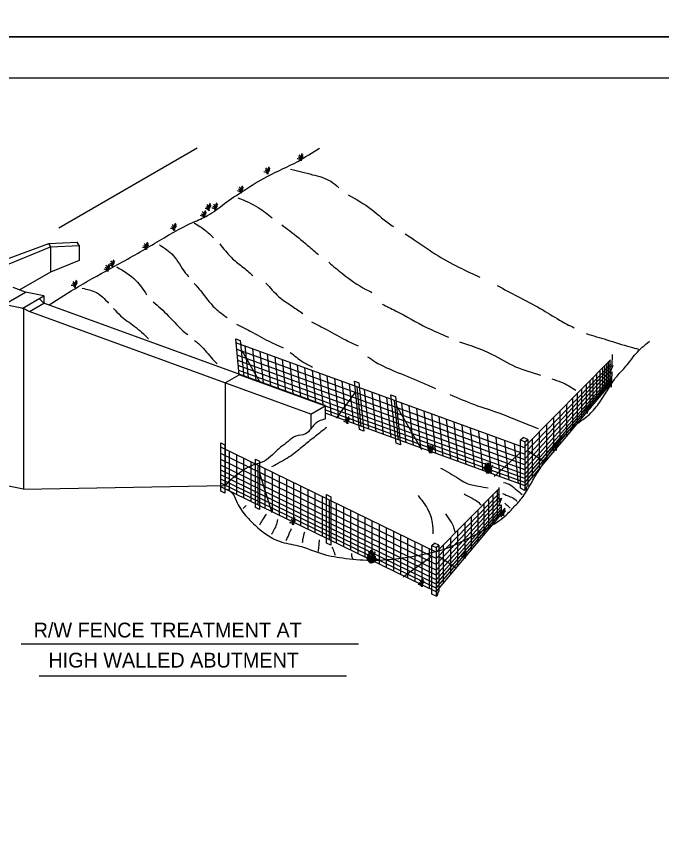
# Model space of a CAD drawing. Extents: x 13 to 918, y -903 to 879.
# Drawn here: x 134.4 to 370, y -602.3 to -301.6 of the extents above; entities that cross this region are included whole.
import ezdxf

# ---------------------------------------------------------------- set-up
doc = ezdxf.new("R2010")
doc.units = 0
for name, color, linetype in [('1', 7, 'Continuous'), ('3', 7, 'Continuous'), ('PLT-BNDY', 7, 'Continuous')]:
    doc.layers.add(name, color=color, linetype=linetype)

msp = doc.modelspace()

# ---------------------------------------------------------------- linework, layer by layer
at = {"layer": '1'}
for p, q in [((146.07275, -384.56525), (156.61225, -384.013)), ((146.904, -385.75275), (146.1915, -384.5215)), ((157.302, -385.20675), (156.61225, -384.013)), ((146.88525, -385.7215), (146.88525, -394.9485)), ((146.904, -385.75275), (157.302, -385.20675)), ((157.302, -385.20675), (157.302, -390.711)), ((136.52275, -408.234), (144.36025, -403.70675)), ((144.36025, -406.361), (142.68725, -404.62975)), ((144.36025, -403.70675), (144.36025, -406.361)), ((136.93525, -408.3235), (136.93525, -474.34425)), ((139.06225, -409.4215), (136.93525, -408.3235)), ((139.19775, -409.34225), (144.36025, -406.361)), ((215.77475, -432.48175), (214.53325, -419.409)), ((214.53325, -419.409), (216.07275, -419.9735)), ((216.07275, -419.9735), (217.479, -433.159)), ((216.6895, -423.60475), (223.18525, -434.8965)), ((217.86225, -421.92775), (219.079, -433.49425)), ((220.57475, -423.00475), (221.78325, -434.49225)), ((223.29775, -423.9965), (224.50825, -435.48175)), ((226.02275, -424.99025), (227.23725, -436.534)), ((228.7435, -425.97975), (229.95825, -437.511)), ((231.4665, -426.96725), (232.68725, -438.588)), ((352.004, -425.09425), (351.8915, -429.234)), ((234.1935, -427.963), (235.402, -439.461)), ((236.9145, -428.95275), (238.13325, -440.536)), ((239.6415, -429.94425), (240.8435, -441.39025)), ((348.454, -430.0255), (348.454, -439.4255)), ((349.14775, -429.3235), (349.14775, -438.50275)), ((349.85825, -428.60475), (349.85825, -437.69425)), ((350.51225, -427.94225), (350.51225, -436.79025)), ((351.18725, -427.259), (351.18725, -436.136)), ((210.61225, -435.463), (215.77475, -432.48175)), ((242.36225, -430.934), (243.57475, -442.4755)), ((245.08725, -431.92775), (246.28725, -443.361)), ((247.81025, -432.91925), (249.32475, -447.31925)), ((346.26225, -432.24225), (346.26225, -442.00275)), ((347.43525, -431.05675), (347.43525, -440.6965)), ((351.829, -431.5235), (351.679, -437.06925)), ((210.61225, -435.463), (210.61225, -472.91925)), ((250.53525, -433.90675), (252.04775, -448.311)), ((253.25825, -434.9005), (254.77075, -449.30275)), ((255.981, -435.89225), (257.4935, -450.29425)), ((259.68325, -452.4755), (257.829, -434.861)), ((257.829, -434.861), (259.4665, -435.45675)), ((259.4665, -435.45675), (261.3165, -453.06925)), ((343.781, -434.75475), (343.781, -444.888)), ((344.89575, -433.6255), (344.89575, -443.58175)), ((258.28525, -438.763), (251.18325, -448.2965)), ((258.702, -436.884), (260.2165, -451.286)), ((261.429, -437.8755), (262.9415, -452.2755)), ((264.14975, -438.86525), (265.6645, -453.26925)), ((340.8435, -437.7255), (340.8435, -448.38175)), ((342.44775, -436.10275), (342.44775, -446.53175)), ((266.877, -439.859), (268.3895, -454.259)), ((269.59775, -440.8465), (271.11225, -455.2505)), ((273.03325, -457.47775), (271.179, -439.863)), ((271.179, -439.863), (272.8165, -440.459)), ((272.32275, -441.84025), (273.83525, -456.24225)), ((272.8165, -440.459), (274.6665, -458.0715)), ((337.49775, -441.113), (337.49775, -452.534)), ((339.256, -439.33175), (339.256, -450.25675)), ((241.93525, -446.861), (247.09775, -443.87975)), ((247.1395, -443.76725), (247.1395, -448.6985)), ((273.302, -444.0715), (282.3645, -459.81925)), ((275.04575, -442.82975), (276.56025, -457.23175)), ((277.77075, -443.8215), (279.28325, -458.2255)), ((280.4935, -444.81525), (282.006, -459.21525)), ((335.29575, -443.34025), (335.29575, -455.14025)), ((241.93525, -446.861), (241.93525, -452.2215)), ((283.2165, -445.80475), (284.731, -460.209)), ((285.93725, -446.79425), (287.452, -461.1985)), ((288.6645, -447.79025), (290.179, -462.19025)), ((332.8665, -445.7985), (332.8665, -458.011)), ((291.38525, -448.77775), (292.89975, -463.17975)), ((294.11225, -449.76925), (295.62075, -464.138)), ((297.056, -450.9235), (298.5645, -465.29225)), ((327.9435, -450.77975), (327.9435, -463.85675)), ((330.54975, -448.14225), (330.54975, -460.7505)), ((261.3165, -453.06925), (259.68325, -452.4755)), ((300.17075, -452.0215), (301.679, -466.39025)), ((303.21025, -453.1755), (304.7185, -467.54425)), ((325.3395, -453.41525), (325.3395, -466.961)), ((306.327, -454.32975), (307.83525, -468.6985)), ((309.4435, -455.484), (310.952, -469.85275)), ((312.7145, -456.57975), (314.22275, -470.9485)), ((318.554, -473.961), (318.554, -456.25275)), ((318.554, -456.25275), (320.1165, -457.01525)), ((320.1165, -457.01525), (320.1165, -474.7235)), ((321.1415, -456.159), (321.1415, -472.938)), ((322.73325, -456.05275), (322.73325, -470.06525)), ((208.99775, -475.0255), (208.99775, -457.31725)), ((208.99775, -457.31725), (210.56025, -458.07975)), ((210.56025, -458.07975), (210.56025, -475.788)), ((274.6665, -458.0715), (273.03325, -457.47775)), ((316.19575, -457.811), (317.704, -472.17975)), ((320.129, -458.688), (320.129, -471.86525)), ((321.10825, -460.14425), (327.40825, -464.32975)), ((212.14975, -460.49225), (212.14975, -474.9735)), ((214.756, -461.763), (214.756, -476.24425)), ((217.36025, -463.034), (217.36025, -477.51525)), ((318.552, -460.886), (308.8665, -469.61525)), ((219.9665, -464.30475), (219.9665, -478.786)), ((221.652, -481.013), (221.652, -463.30475)), ((221.652, -463.30475), (223.2145, -464.06725)), ((222.57075, -465.5755), (222.57075, -480.05675)), ((223.2145, -464.06725), (223.2145, -481.7755)), ((223.227, -468.42975), (227.729, -482.85675)), ((225.17475, -466.84425), (225.17475, -481.3255)), ((227.781, -468.11525), (227.781, -482.5965)), ((230.38525, -469.386), (230.38525, -483.86725)), ((232.9915, -470.65675), (232.9915, -485.138)), ((235.59575, -471.92775), (235.59575, -486.409)), ((136.93525, -474.34425), (210.61225, -472.91925)), ((210.56025, -475.788), (208.99775, -475.0255)), ((238.19975, -473.1985), (238.19975, -487.67975)), ((240.806, -474.46925), (240.806, -488.9505)), ((310.0145, -474.8255), (310.0145, -485.18175)), ((310.61225, -473.63175), (310.61225, -478.05275)), ((320.1165, -474.7235), (318.554, -473.961)), ((243.41025, -475.738), (243.41025, -490.21925)), ((246.0165, -477.009), (246.0165, -491.49025)), ((247.6935, -493.984), (247.6935, -476.2755)), ((247.6935, -476.2755), (249.256, -477.038)), ((249.256, -477.038), (249.256, -494.7465)), ((306.82275, -477.98175), (306.82275, -488.90675)), ((308.41025, -476.3755), (308.41025, -487.03175)), ((223.2145, -481.7755), (221.652, -481.013)), ((248.62075, -478.27975), (248.62075, -492.761)), ((251.22475, -479.5505), (251.22475, -494.03175)), ((253.831, -480.8215), (253.831, -495.30275)), ((305.0645, -479.763), (305.0645, -491.184)), ((311.42275, -479.9715), (311.42275, -484.51925)), ((256.43525, -482.09225), (256.43525, -496.5735)), ((259.0415, -483.363), (259.0415, -497.84425)), ((302.86225, -481.99025), (302.86225, -493.79025)), ((261.64575, -484.63175), (261.64575, -499.113)), ((264.24975, -485.90275), (264.24975, -500.384)), ((266.856, -487.1735), (266.856, -501.65475)), ((298.1165, -486.79225), (298.1165, -499.4005)), ((300.43325, -484.4485), (300.43325, -496.661)), ((269.46025, -488.44425), (269.46025, -502.9255)), ((272.0665, -489.71525), (272.0665, -504.1965)), ((295.51025, -489.42975), (295.51025, -502.50675)), ((274.67075, -490.986), (274.67075, -505.46725)), ((277.27475, -492.25475), (277.27475, -506.736)), ((292.906, -492.06525), (292.906, -505.611)), ((249.256, -494.7465), (247.6935, -493.984)), ((279.881, -493.52775), (279.881, -508.009)), ((282.48525, -494.7965), (282.48525, -509.27775)), ((285.0915, -496.06725), (285.0915, -510.51525)), ((286.12075, -512.611), (286.12075, -494.90275)), ((286.12075, -494.90275), (287.68325, -495.66525)), ((287.68325, -495.66525), (287.68325, -513.3735)), ((288.70825, -494.809), (288.70825, -511.588)), ((290.29975, -494.70275), (290.29975, -508.71525)), ((286.1915, -498.75275), (275.64775, -506.4215)), ((287.69575, -497.338), (287.69575, -510.51525)), ((288.67475, -498.79425), (294.97475, -502.97975)), ((287.68325, -513.3735), (286.12075, -512.611))]:
    msp.add_line(p, q, dxfattribs=at)
for points in [[(837.2505, -888.06975), (837.2505, -324.06975), (51.2505, -324.06975), (51.2505, -888.06975), (837.2505, -888.06975), (837.2505, -861.71075), (637.2505, -861.71075), (637.2505, -797.03325), (837.2505, -797.03325), (837.2505, -768.06975), (637.2505, -768.06975), (637.2505, -888.06975), (716.052, -888.06975), (716.052, -861.71075), (716.052, -888.06975), (793.052, -888.06975), (793.052, -861.71075), (793.052, -874.02725), (837.2505, -874.02725)], [(351.2935, -429.47975), (352.24975, -429.05275), (351.1915, -431.80675), (352.14775, -431.37975)], [(306.62275, -468.59225), (308.2185, -465.5715), (306.277, -468.41925), (307.58325, -464.99425), (306.58325, -468.55275), (306.9685, -464.686), (306.3145, -468.34225), (306.277, -464.66725), (306.6415, -468.51525), (305.62275, -464.763), (306.277, -468.45675), (305.429, -465.8215), (306.681, -468.45675), (305.27475, -466.611), (306.23725, -468.45675), (308.04575, -466.59225), (306.54575, -468.4965), (308.19975, -467.59225), (306.23725, -468.361)], [(320.1165, -474.686), (320.5685, -474.45475), (320.68525, -474.0715), (320.72275, -473.59025), (320.954, -473.3215), (321.0685, -473.03175), (321.1415, -472.91725)], [(310.5685, -478.0715), (311.52475, -477.64425), (310.4665, -480.3985), (311.42275, -479.9715)], [(287.68325, -513.336), (288.13525, -513.10475), (288.252, -512.7215), (288.2895, -512.24025), (288.52075, -511.9715), (288.63525, -511.68175), (288.70825, -511.56725)]]:
    msp.add_lwpolyline(points, dxfattribs=at)
for centre, radius, start, end in [((240.74523, -353.29065), 2.54574, 139.3976806, 202.1514389), ((236.91991, -355.22506), 1.68722, 34.5049889, 89.1232639), ((237.13052, -354.07945), 1.15481, 346.635825, 79.9956111), ((236.0146, -353.71526), 2.32168, 344.7066778, 44.9317139), ((239.81735, -354.14027), 1.53965, 118.5656389, 187.6931111), ((241.70484, -354.22605), 3.37523, 142.0984694, 181.7245194), ((224.99302, -358.92737), 1.15481, 346.635825, 79.9956111), ((223.8771, -358.56317), 2.32168, 344.7066778, 44.9317139), ((228.60773, -358.13857), 2.54574, 139.3976806, 202.1514389), ((227.67985, -358.98818), 1.53965, 118.5656389, 187.6931111), ((229.56734, -359.07397), 3.37523, 142.0984694, 181.7245194), ((224.78241, -360.07298), 1.68722, 34.5049889, 89.1232639), ((214.16251, -365.50692), 2.32168, 344.7066778, 44.9317139), ((218.89315, -365.08232), 2.54574, 139.3976806, 202.1514389), ((215.06782, -367.01673), 1.68722, 34.5049889, 89.1232639), ((215.27844, -365.87112), 1.15481, 346.635825, 79.9956111), ((217.96526, -365.93193), 1.53965, 118.5656389, 187.6931111), ((219.85276, -366.01772), 3.37523, 142.0984694, 181.7245194), ((207.10148, -371.48857), 2.54574, 139.3976806, 202.1514389), ((209.54315, -371.31565), 2.54574, 139.3976806, 202.1514389), ((200.6396, -374.52984), 2.32168, 344.7066778, 44.9317139), ((205.37023, -374.10524), 2.54574, 139.3976806, 202.1514389), ((203.27616, -373.42298), 1.68722, 34.5049889, 89.1232639), ((203.48677, -372.27737), 1.15481, 346.635825, 79.9956111), ((202.37085, -371.91317), 2.32168, 344.7066778, 44.9317139), ((206.1736, -372.33818), 1.53965, 118.5656389, 187.6931111), ((208.06109, -372.42397), 3.37523, 142.0984694, 181.7245194), ((205.71782, -373.25006), 1.68722, 34.5049889, 89.1232639), ((205.92844, -372.10445), 1.15481, 346.635825, 79.9956111), ((204.81251, -371.74026), 2.32168, 344.7066778, 44.9317139), ((208.61526, -372.16527), 1.53965, 118.5656389, 187.6931111), ((210.50276, -372.25105), 3.37523, 142.0984694, 181.7245194), ((201.54491, -376.03965), 1.68722, 34.5049889, 89.1232639), ((201.75552, -374.89404), 1.15481, 346.635825, 79.9956111), ((204.44235, -374.95485), 1.53965, 118.5656389, 187.6931111), ((206.32984, -375.04063), 3.37523, 142.0984694, 181.7245194), ((190.84719, -379.56695), 1.15481, 346.635825, 79.9956111), ((189.73126, -379.20276), 2.32168, 344.7066778, 44.9317139), ((194.4619, -378.77815), 2.54574, 139.3976806, 202.1514389), ((193.53401, -379.62777), 1.53965, 118.5656389, 187.6931111), ((195.42151, -379.71355), 3.37523, 142.0984694, 181.7245194), ((190.63657, -380.71256), 1.68722, 34.5049889, 89.1232639), ((179.49793, -386.12984), 2.32168, 344.7066778, 44.9317139), ((184.22857, -385.70524), 2.54574, 139.3976806, 202.1514389), ((185.18818, -386.64063), 3.37523, 142.0984694, 181.7245194), ((180.40324, -387.63965), 1.68722, 34.5049889, 89.1232639), ((180.61386, -386.49404), 1.15481, 346.635825, 79.9956111), ((183.30068, -386.55485), 1.53965, 118.5656389, 187.6931111), ((167.18543, -392.55484), 2.32168, 344.7066778, 44.9317139), ((171.91607, -392.13024), 2.54574, 139.3976806, 202.1514389), ((166.35949, -395.6209), 1.68722, 34.5049889, 89.1232639), ((166.57011, -394.47529), 1.15481, 346.635825, 79.9956111), ((165.45418, -394.11109), 2.32168, 344.7066778, 44.9317139), ((170.18482, -393.68649), 2.54574, 139.3976806, 202.1514389), ((169.25693, -394.5361), 1.53965, 118.5656389, 187.6931111), ((171.14443, -394.62188), 3.37523, 142.0984694, 181.7245194), ((168.09074, -394.06465), 1.68722, 34.5049889, 89.1232639), ((168.30136, -392.91904), 1.15481, 346.635825, 79.9956111), ((170.98818, -392.97985), 1.53965, 118.5656389, 187.6931111), ((172.87568, -393.06563), 3.37523, 142.0984694, 181.7245194), ((154.39491, -401.5084), 1.68722, 34.5049889, 89.1232639), ((154.60552, -400.36279), 1.15481, 346.635825, 79.9956111), ((153.4896, -399.99859), 2.32168, 344.7066778, 44.9317139), ((158.22023, -399.57399), 2.54574, 139.3976806, 202.1514389), ((157.29235, -400.4236), 1.53965, 118.5656389, 187.6931111), ((159.17984, -400.50938), 3.37523, 142.0984694, 181.7245194), ((340.79262, -446.03759), 1.97401, 340.3763778, 56.4624917), ((337.53479, -445.41441), 5.30578, 346.3887194, 18.8456472), ((345.42541, -445.59079), 2.73341, 125.7872472, 200.4625444), ((345.24911, -446.22664), 2.46318, 129.7876167, 190.205025), ((257.73273, -449.33857), 2.54574, 139.3976806, 202.1514389), ((341.12625, -447.03952), 1.70327, 12.7696972, 59.9544917), ((253.90741, -451.27298), 1.68722, 34.5049889, 89.1232639), ((254.11802, -450.12737), 1.15481, 346.635825, 79.9956111), ((253.0021, -449.76317), 2.32168, 344.7066778, 44.9317139), ((256.80485, -450.18818), 1.53965, 118.5656389, 187.6931111), ((258.69234, -450.27397), 3.37523, 142.0984694, 181.7245194), ((336.05809, -459.22027), 4.6144, 144.0455, 192.5566278), ((280.94652, -462.14109), 4.99917, 11.477125, 44.0518528), ((262.0893, -467.8557), 24.25855, 16.1942278, 22.2630333), ((251.95983, -464.84735), 33.62974, 6.3182278, 11.4283389), ((275.78806, -461.73646), 9.86983, 3.87595, 20.7342222), ((292.74066, -460.66782), 7.44782, 161.6192222, 183.6840556), ((287.12805, -460.85639), 1.55615, 91.1135861, 190.0377389), ((295.87435, -459.95762), 10.29921, 170.6355361, 186.1964472), ((288.75293, -460.46429), 2.98614, 135.1656, 193.2039417), ((287.89253, -461.23684), 2.07234, 110.8760639, 175.3625472), ((290.95729, -460.57271), 4.85599, 152.8772472, 186.7845), ((329.56301, -460.00959), 1.92587, 353.6243139, 68.0395306), ((329.0399, -459.24325), 2.61305, 338.852575, 40.9169944), ((339.06378, -461.40083), 7.7538, 150.3862972, 171.2661556), ((333.70568, -460.09978), 2.1929, 126.5456194, 182.2521944), ((310.82824, -484.86048), 1.68722, 34.5049889, 89.1232639), ((311.03886, -483.71487), 1.15481, 346.635825, 79.9956111), ((309.92293, -483.35067), 2.32168, 344.7066778, 44.9317139), ((314.65357, -482.92607), 2.54574, 139.3976806, 202.1514389), ((313.72568, -483.77568), 1.53965, 118.5656389, 187.6931111), ((315.61318, -483.86147), 3.37523, 142.0984694, 181.7245194), ((234.13241, -488.26465), 1.68722, 34.5049889, 89.1232639), ((234.34302, -487.11904), 1.15481, 346.635825, 79.9956111), ((233.2271, -486.75484), 2.32168, 344.7066778, 44.9317139), ((237.95773, -486.33024), 2.54574, 139.3976806, 202.1514389), ((237.02985, -487.17985), 1.53965, 118.5656389, 187.6931111), ((238.91734, -487.26563), 3.37523, 142.0984694, 181.7245194), ((296.80532, -500.51881), 1.68722, 34.5049889, 89.1232639), ((297.01594, -499.3732), 1.15481, 346.635825, 79.9956111), ((295.90001, -499.00901), 2.32168, 344.7066778, 44.9317139), ((300.63065, -498.5844), 2.54574, 139.3976806, 202.1514389), ((299.70276, -499.43402), 1.53965, 118.5656389, 187.6931111), ((301.59026, -499.5198), 3.37523, 142.0984694, 181.7245194), ((280.1646, -509.30067), 2.32168, 344.7066778, 44.9317139), ((284.89523, -508.87607), 2.54574, 139.3976806, 202.1514389), ((285.85484, -509.81147), 3.37523, 142.0984694, 181.7245194), ((281.06991, -510.81048), 1.68722, 34.5049889, 89.1232639), ((281.28052, -509.66487), 1.15481, 346.635825, 79.9956111), ((283.96735, -509.72568), 1.53965, 118.5656389, 187.6931111)]:
    msp.add_arc(centre, radius, start, end, dxfattribs=at)
for points in [[(146.30825, -406.98175), (157.056, -400.2255), (170.40825, -392.74225), (184.9685, -384.4505), (198.9165, -376.7755), (204.1685, -374.3505), (210.4395, -369.90675), (217.32475, -365.25275), (226.02075, -360.0005), (237.1395, -354.538), (245.027, -349.6715)], [(234.5415, -357.384), (242.5645, -359.386), (249.181, -361.79025), (252.204, -364.12975)], [(255.53525, -366.686), (264.01225, -372.0235), (271.631, -378.0255), (272.12475, -378.336)], [(215.306, -367.811), (222.731, -371.409), (227.77475, -375.1255)], [(199.281, -377.0255), (203.28325, -379.64225), (206.3665, -382.4735)], [(231.32075, -377.7485), (234.1395, -379.834), (240.756, -385.24025), (244.73725, -388.64425)], [(276.352, -380.99425), (278.63325, -382.42975), (287.252, -388.259), (296.081, -393.261), (303.6915, -396.79025)], [(208.679, -384.6985), (212.902, -389.64425), (216.7685, -392.8755), (220.78725, -396.28175)], [(186.6435, -385.0465), (191.6645, -388.85475), (196.0685, -395.261), (197.34575, -396.76525)], [(171.02275, -393.06925), (178.02475, -398.06925), (181.9395, -403.22975)], [(248.44775, -391.3985), (253.606, -395.66525), (262.01225, -401.28175), (264.252, -402.4005)], [(199.329, -399.10275), (201.68525, -401.87975), (206.879, -408.09225), (211.3415, -411.60675)], [(225.43525, -398.963), (225.5395, -399.06925), (230.156, -403.87975), (235.15825, -407.4755), (238.97475, -410.05675)], [(310.002, -399.911), (317.529, -403.87975), (325.7435, -408.284), (332.7645, -412.4985), (338.1145, -415.36525)], [(158.38525, -400.87775), (163.59775, -402.4755), (168.002, -406.284)], [(184.32475, -405.85475), (189.856, -410.9005), (194.6645, -415.90275), (196.96025, -417.82775)], [(169.88725, -408.259), (172.40825, -410.9005), (177.429, -414.709), (182.6415, -419.30675)], [(267.952, -406.661), (272.82275, -409.09225), (284.46225, -415.30675), (292.256, -418.76525)], [(214.802, -413.9735), (220.5185, -416.90275), (227.5395, -420.711), (231.8165, -422.709)], [(242.15825, -413.16525), (247.87475, -416.09425), (254.89575, -419.90275), (259.17275, -421.9005)], [(342.5435, -417.46525), (350.002, -419.711), (358.6185, -422.32775), (361.62075, -423.11725)], [(199.456, -419.9215), (200.879, -421.11525), (205.49575, -426.136), (207.68725, -428.54025)], [(211.42075, -474.3235), (213.402, -475.959), (215.03725, -479.2485), (218.63325, -484.5005), (222.577, -488.4255), (230.44575, -493.3505), (237.331, -494.984), (246.181, -497.9465), (254.72075, -499.58175), (264.879, -500.236), (274.054, -499.58175), (283.84575, -497.9465), (290.2145, -496.3505), (295.677, -494.07975), (300.69775, -491.57975), (306.527, -488.4255), (312.75825, -484.1735), (316.356, -480.55675), (318.954, -477.613), (322.35825, -472.209), (325.22475, -467.438), (330.78325, -458.78175), (334.78525, -454.35675), (338.3435, -451.0485), (344.231, -446.4505), (347.84575, -441.8715), (351.46225, -436.29425), (353.752, -433.00475), (357.02275, -429.40675), (360.6395, -424.809), (365.5645, -420.23175)], [(296.206, -420.436), (307.91025, -424.9255), (316.72075, -429.54225), (325.827, -432.584)], [(234.42475, -424.30275), (238.9665, -427.734), (242.5645, -429.734)], [(262.64575, -425.888), (265.4165, -427.734), (273.82275, -431.734), (283.05825, -435.54225), (287.504, -437.46525)], [(329.9685, -433.9965), (333.36225, -435.159), (338.7665, -438.159)], [(292.72075, -439.7005), (301.69775, -443.3735), (310.91225, -446.56525), (317.529, -449.18175), (324.93525, -452.184)], [(247.1395, -448.6985), (244.83325, -449.4715), (241.93525, -452.2215), (239.9665, -454.10675), (236.3895, -454.95275), (233.63725, -456.85675), (230.88725, -458.9735), (227.92475, -461.7235), (224.96225, -464.05275), (221.3645, -465.3215), (218.21025, -466.80275), (215.46025, -468.70675), (213.7665, -469.97775), (210.61225, -472.91925)], [(247.604, -451.759), (243.602, -454.9715), (239.58325, -458.16525), (235.3895, -461.59025), (229.77075, -464.99425), (227.56025, -466.188)], [(289.2895, -466.59225), (295.90825, -470.4005), (298.52275, -471.9965), (303.12075, -473.209), (306.73725, -473.80475)], [(312.3165, -471.8235), (314.91225, -472.8235), (317.12475, -474.63175), (319.127, -476.22975)], [(281.077, -476.613), (284.481, -481.4235), (286.2895, -486.636), (286.481, -490.638)], [(297.8895, -476.036), (300.8895, -477.634), (302.2935, -478.44025), (304.102, -480.038)], [(311.91225, -475.84425), (314.72075, -477.036), (316.529, -478.038), (317.3185, -478.84425)], [(218.34575, -480.22975), (217.9415, -480.61525), (217.152, -481.4235)], [(312.72075, -479.44225), (313.91225, -480.44225), (314.72075, -481.2505)], [(225.55825, -483.4235), (224.154, -485.636), (223.154, -487.44425)], [(291.06025, -483.2505), (293.079, -486.2505), (294.079, -488.2715), (294.48325, -489.86725)], [(229.77075, -485.4235), (229.17475, -487.636), (228.17475, -489.636), (227.56025, -490.8485)], [(234.77275, -488.8485), (234.177, -490.04025), (233.581, -491.44425), (232.77275, -493.04225)], [(239.58325, -490.04025), (238.98525, -492.4465), (238.7935, -493.8505)], [(245.00825, -492.8485), (244.79575, -494.8505), (244.604, -497.063)], [(249.604, -495.4465), (250.41225, -497.25475), (250.8165, -498.46725)], [(256.8185, -497.8505), (256.8185, -498.659), (257.22275, -499.8715)], [(263.83325, -501.05275), (265.29775, -497.313), (264.1435, -501.213), (264.502, -496.79425), (263.78525, -501.088), (263.78525, -496.5965), (264.06225, -501.16725), (263.152, -496.99025), (263.78525, -501.134), (262.677, -498.02775), (264.06225, -501.213), (262.32075, -499.05675), (263.78525, -501.16725), (265.57475, -498.8255), (264.1895, -501.16725), (265.77075, -500.059), (263.704, -501.05275)]]:
    msp.add_spline(points, degree=3, dxfattribs=at)
at = {"layer": '3'}
for p, q in [((149.83525, -378.809), (200.42275, -349.60475)), ((128.48325, -391.10675), (146.1915, -384.5215)), ((129.69775, -392.84025), (146.831, -385.74425)), ((146.99975, -394.88175), (157.42275, -390.663)), ((135.556, -401.488), (146.99975, -394.88175)), ((129.93325, -406.759), (137.70825, -402.2715)), ((137.70825, -402.2715), (133.2395, -400.64425)), ((144.36025, -403.70675), (137.704, -402.26925)), ((136.93525, -408.3235), (130.279, -406.886)), ((247.1395, -443.76725), (144.36025, -406.361)), ((241.93525, -446.861), (139.06225, -409.4215)), ((320.1165, -459.23175), (214.556, -420.81525)), ((214.94575, -423.1715), (319.852, -461.35275)), ((320.1165, -463.52975), (215.02475, -425.27775)), ((320.129, -458.688), (351.38725, -427.05675)), ((320.1165, -465.463), (215.23525, -427.29025)), ((320.1165, -467.26725), (215.43325, -429.163)), ((320.129, -461.00275), (351.4435, -428.59425)), ((320.129, -463.1755), (351.5395, -429.65275)), ((320.1165, -468.93175), (215.6145, -430.89225)), ((320.1165, -470.4505), (215.781, -432.47775)), ((320.129, -465.2005), (351.5395, -430.76925)), ((320.129, -467.084), (351.59775, -431.98175)), ((320.129, -468.8235), (351.656, -433.19225)), ((320.129, -470.41525), (351.88725, -433.86725)), ((320.129, -471.86525), (351.88725, -434.57775)), ((320.129, -473.16925), (351.79575, -435.43175)), ((320.1165, -471.84025), (247.08325, -445.25675)), ((320.177, -473.113), (247.09975, -446.509)), ((318.554, -456.25275), (319.531, -455.3735)), ((321.1415, -456.159), (319.531, -455.3735)), ((320.1165, -457.01525), (321.1415, -456.159)), ((287.69575, -497.338), (208.99775, -458.95475)), ((287.69575, -499.65275), (208.99775, -461.26925)), ((287.69575, -501.8255), (208.99775, -463.44225)), ((287.69575, -503.8505), (208.99775, -465.46725)), ((287.69575, -505.734), (208.99775, -467.3505)), ((287.69575, -507.4735), (208.99775, -469.09025)), ((287.69575, -509.06525), (208.99775, -470.68175)), ((287.69575, -510.51525), (208.99775, -472.13175)), ((136.93525, -474.34425), (130.279, -472.90675)), ((287.69575, -511.81925), (208.99775, -473.436)), ((287.69575, -497.338), (310.4915, -474.2715)), ((287.69575, -499.65275), (310.58725, -475.963)), ((287.69575, -501.8255), (310.62075, -477.361)), ((287.69575, -503.8505), (311.2395, -478.04225)), ((287.69575, -505.734), (310.606, -480.17975)), ((287.69575, -507.4735), (311.3145, -480.78175)), ((287.69575, -509.06525), (311.37075, -481.81925)), ((287.69575, -510.51525), (311.52475, -482.538)), ((287.69575, -511.81925), (311.38325, -483.59025)), ((286.12075, -494.90275), (287.09775, -494.0235)), ((288.70825, -494.809), (287.09775, -494.0235)), ((287.68325, -495.66525), (288.70825, -494.809)), ((136.09975, -530.7755), (259.34775, -530.7755)), ((142.68325, -542.488), (254.96025, -542.488))]:
    msp.add_line(p, q, dxfattribs=at)
at = {"layer": 'PLT-BNDY'}
for points in [[(13.2505, 284.93025), (854.2505, 284.93025), (854.2505, -309.06975), (13.2505, -309.06975)], [(13.2505, -309.06975), (854.2505, -309.06975), (854.2505, -903.06975), (13.2505, -903.06975)]]:
    msp.add_lwpolyline(points, close=True, dxfattribs=at)

# ---------------------------------------------------------------- texts
at = {"layer": '3'}
for s, p in [('R/W FENCE TREATMENT AT', (140.681, -528.47775)), ('HIGH WALLED ABUTMENT', (146.056, -539.46925))]:
    msp.add_text(s, height=5.4020865, dxfattribs=at).set_placement(p)

doc.saveas('drawing.dxf')
